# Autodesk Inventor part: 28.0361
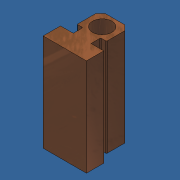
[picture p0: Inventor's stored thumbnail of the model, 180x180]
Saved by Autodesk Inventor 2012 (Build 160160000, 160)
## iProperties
Created: 2011-09
Part Number: 28.0361
Document SubType Name: Modeling
Designer: Administrator
Density: 8.47 g/cm^3
Mass: 113.337 g
Surface Area: 64.2999 cm^2
Volume: 13.3809 cm^3
Material: Brass, Soft Yellow
Description: MINI ADJ CARRIAGE
Vendor: S
Author: Administrator
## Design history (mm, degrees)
node "Base1"
sketch "Sketch1"
  geometry: C1 r 3.682 at (10, 17.3) reference; C2 r 4.5 at (10, 17.3); 1 further point
  constraints: 1 centre point, 1 coincident
  dimensions: "d0" = 9 diameter of C2
extrude "Extrusion1" cut sketch "Sketch1" distance "d1" = 16; taper "d2" = 0 deg
sketch "Sketch2"
  geometry: C1 r 3.682 at (10, -17.3) reference; C2 r 4.5 at (10, -17.3); 1 further point
  constraints: 1 centre point, 1 coincident
  dimensions: "d3" = 9 diameter of C2
extrude "Extrusion2" cut sketch "Sketch2" distance "d4" = 16; taper "d5" = 0 deg
body "Solid1"
